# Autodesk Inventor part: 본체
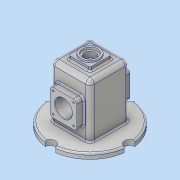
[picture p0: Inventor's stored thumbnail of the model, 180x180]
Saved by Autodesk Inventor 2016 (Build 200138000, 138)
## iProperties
Created: 2018-07
Part Number: 본체
Material: 알루미늄 6061
Document SubType Name: Modeling
Designer: 605-17
Density: 2.7 g/cm^3
Appearance: 알루미늄 - 평지
Mass: 909.367 g
Surface Area: 1016.32 cm^2
Volume: 336.803 cm^3
Author: 605-17
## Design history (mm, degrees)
sketch "스케치1"
  geometry: L1 (-37, 55)-(37, 55); L2 (37, 55)-(37, -55); L3 (37, -55)-(-37, -55); L4 (-37, -55)-(-37, 55); 3 further points
  constraints: 8 end point, 2 midpoint, 2 parallel, 1 horizontal, 1 horizontal alignment, 1 perpendicular, 1 vertical alignment
  dimensions: "d0" = 74 distance of L1.start L1.end; "d1" = 110 distance of L1.end L2.end
extrude "돌출1" new body sketch "스케치1" stored distance "d2" = 74; taper "d3" = 0 deg
fillet "모깎기1" dims "d4" = 8
fillet "모깎기2" dims "d5" = 8
feature "쉘1" dims "d6" = 5
node "작업 평면1"
sketch "스케치2"
  geometry: L1 (-25, 25)-(25, 25); L2 (25, 25)-(25, -25); L3 (25, -25)-(-25, -25); L4 (-25, -25)-(-25, 25); 3 further points
  constraints: 8 end point, 2 midpoint, 2 parallel, 2 perpendicular, 1 horizontal, 1 horizontal alignment, 1 vertical alignment
  dimensions: "d8" = 50 distance of L1.start L1.end
extrude "돌출2" join sketch "스케치2" stored distance "d9" = 74; taper "d10" = 0 deg
sketch "스케치3"
  geometry: L1 (0, 50)-(0, -50); L2 (25, 32)-(22.452, 25); L3 (22.452, 25)-(16, 25); L4 (25, 32)-(16, 32); L5 (0, 50)-(16, 50); L6 (16, 50)-(16, 32); L7 (-55, 32)-(47, 32) reference; L8 (0, 0)-(16, 0); L9 (16, 0)-(16, 25); 1 further point
  constraints: 16 end point, 2 horizontal, 2 perpendicular, 1 coincident, 1 horizontal alignment, 1 midpoint, 1 vertical, 1 vertical alignment
  dimensions: "d11" = 100 distance of L1.start L1.end; "d14" = 110 deg angle of L2 L3; "d15" = 50 diameter of L2.start L1; "d18" = 9 distance of L2.start L4.end; "d19" = 32 diameter of L9 L1; "d20" = 6.45221 distance of L2.end L3.end; "d21" = 16 distance of L1.start L5.end
revolve "회전1" sketch "스케치3" stored, may be unused: angle "d22" = 90 deg
sketch "스케치4"
  geometry: C1 r 16 at (0, 0); 1 further point
  constraints: 1 centre point, 1 coincident
  dimensions: "d23" = 32 diameter of C1
extrude "돌출3" cut sketch "스케치4" distance "d24" = 100; taper "d25" = 0 deg
node "작업 평면2"
sketch "스케치5"
  geometry: L1 (29, 32)-(-29, 32) reference; L2 (-32, 29)-(-32, -29) reference; L3 (-29, -32)-(29, -32) reference; L4 (32, -29)-(32, 29) reference; L5 (-29, -37)-(29, -37) reference; L6 (-37, 29)-(-37, -29) reference; L7 (29, 37)-(-29, 37) reference; L8 (37, 29)-(37, -29) reference; A1 r 10 centre (0, -75) between (9.978, -74.333) and (-9.978, -74.333); A2 r 10 centre (-75, 0) between (-74.333, -9.978) and (-74.333, 9.978); A3 r 10 centre (0, 75) between (-9.978, 74.333) and (9.978, 74.333); A4 r 10 centre (75, 0) between (74.333, 9.978) and (74.333, -9.978); A5 r 75 centre (0, 0) between (74.333, 9.978) and (9.978, 74.333); A6 r 75 centre (0, 0) between (-9.978, 74.333) and (-74.333, 9.978); A7 r 75 centre (0, 0) between (-74.333, -9.978) and (-9.978, -74.333); A8 r 75 centre (0, 0) between (9.978, -74.333) and (74.333, -9.978); A9 r 3 centre (29, 29) between (32, 29) and (29, 32) reference; A10 r 3 centre (-29, 29) between (-29, 32) and (-32, 29) reference; A11 r 3 centre (-29, -29) between (-32, -29) and (-29, -32) reference; A12 r 3 centre (29, -29) between (29, -32) and (32, -29) reference; A13 r 8 centre (29, -29) between (29, -37) and (37, -29) reference; A14 r 8 centre (-29, -29) between (-37, -29) and (-29, -37) reference; A15 r 8 centre (-29, 29) between (-29, 37) and (-37, 29) reference; A16 r 8 centre (29, 29) between (37, 29) and (29, 37) reference; 1 further point
  constraints: 16 point on circle, 8 centre point, 3 concentric, 3 vertical alignment, 2 horizontal alignment, 1 coincident
  dimensions: "d28" = 20 diameter of A1; "d29" = 20 diameter of A2; "d30" = 20 diameter of A3; "d31" = 20 diameter of A4; "d32" = 75 radius of A5; "d33" = 75 distance of point (0, 0) A1.centre; "d34" = 75 distance of point (0, 0) A3.centre; "d35" = 75 distance of point (0, 0) A4.centre; "d36" = 75 distance of point (0, 0) A2.centre
extrude "돌출4" join sketch "스케치5" distance "d37" = 10; taper "d38" = 0 deg
node "작업 평면3"
sketch "스케치6"
  geometry: L1 (20, -20)-(-20, -20); L2 (-20, -20)-(-20, 20); L3 (-20, 20)-(20, 20); L4 (20, 20)-(20, -20); 3 further points
  constraints: 8 end point, 2 midpoint, 2 parallel, 2 perpendicular, 1 horizontal, 1 horizontal alignment, 1 vertical alignment
  dimensions: "d40" = 40 distance of L1.end L2.end
extrude "돌출5" join sketch "스케치6" stored distance "d41" = 10; taper "d42" = 0 deg
sketch "스케치7"
  geometry: C1 r 17.5 at (0, 0); 1 further point
  constraints: 1 centre point, 1 coincident
  dimensions: "d43" = 35 diameter of C1
extrude "돌출6" join sketch "스케치7" distance "d44" = 3; taper "d45" = 0 deg
hole "구멍1" diameter "d48" = 21; stored, may be unused: countersink angle "d52" = 90 deg, drill point angle "d54" = 118 deg; dims "d46" = 10, "d47" = 10, "d49" = 6, "d50" = 28, "d51" = 4, "d53" = 50
fillet "모깎기3" dims "d55" = 6
sketch "스케치8"
  geometry: A1 r 6 centre (-19, 19) between (-19, 25) and (-25, 19) reference; A2 r 6 centre (19, 19) between (25, 19) and (19, 25) reference; A3 r 6 centre (19, -19) between (19, -25) and (25, -19) reference; A4 r 6 centre (-19, -19) between (-25, -19) and (-19, -25) reference; 1 further point
hole "구멍2" sketch "스케치8" at (-19, 19), (19, 19), (19, -19), (-19, -19) diameter "d56" = 3.242; stored, may be unused: countersink angle "d60" = 90 deg, drill point angle "d62" = 118 deg; dims "d57" = 8, "d58" = 28, "d59" = 4, "d61" = 10
fillet "모깎기4" dims "d63" = 3
fillet "모깎기5" dims "d64" = 3
fillet "모깎기6" dims "d65" = 3
fillet "모깎기7" dims "d66" = 3
chamfer "모따기1" distance "d67" = 1; stored, may be unused: second distance "d68" = 2, angle "d69" = 45 deg
sketch "스케치10"
  geometry: L1 (-24.683, 41.148)-(24.683, 41.148); L2 (24.683, 41.148)-(24.683, 28.852); L3 (24.683, 28.852)-(-24.683, 28.852); L4 (-24.683, 28.852)-(-24.683, 41.148); L5 (37, -42)-(37, 47) reference; L6 (17.5, 65)-(-17.5, 65) reference; 4 further points
  constraints: 2 midpoint, 1 horizontal alignment, 1 vertical alignment, 2 other
  dimensions: "d76" = 49.36532 distance of L1.start L1.end; "d77" = 12.29678 distance of L1.end L2.end; "d78" = 37 distance from line of L5 point (0, 35); "d79" = 30 distance from line of L6 point (0, 35)
feature "엠보싱2" sketch "스케치10" dims "d0" = 74, "d1" = 110, "d80" = 0.5, "d81" = 0
node "솔리드1"
mirror "대칭1"
mirror "대칭2"
mirror "대칭3"
node "투영된 루프1"
other parameters: "d16" = 32, "d26" = -55, "d39" = 62
